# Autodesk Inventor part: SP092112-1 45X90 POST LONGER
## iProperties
Created: 2012-09
Part Number: SP092112-1 45X90 POST LONGER
Material: Aluminum-6061
Description: PROFILE 45X90 UL
Document SubType Name: Modeling
Designer: Administrator
Stock Number: 20.1067 PROFILE 45X90 UL
Density: 2.71 g/cm^3
Mass: 5258.52 g
Surface Area: 21310.1 cm^2
Volume: 1940.41 cm^3
FINISH: CLEAR ANODIZED
Author: Administrator
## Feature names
1. Extrusion1
